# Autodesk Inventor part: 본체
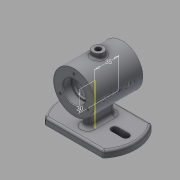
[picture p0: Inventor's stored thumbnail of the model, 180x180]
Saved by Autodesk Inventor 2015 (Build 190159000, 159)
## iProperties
Created: 2017-12
Part Number: 본체
Material: 일반
Document SubType Name: Modeling
Designer: SCD-A03
Density: 1 g/cm^3
Appearance: 기본값
Author: SCD-A03
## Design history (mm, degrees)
sketch "스케치1"
  geometry: L1 (-55, 0)-(55, 0); L2 (-42.426, 35)-(42.426, 35); L3 (-42.426, -35)-(42.426, -35); A1 r 55 centre (0, 0) between (-42.426, 35) and (-42.426, -35); A2 r 55 centre (0, 0) between (42.426, -35) and (42.426, 35); 1 further point
  constraints: 6 end point, 6 point on circle, 2 centre point, 2 parallel, 1 coincident, 1 horizontal
  dimensions: "d1" = 35 distance between parallel lines of L3 L1; "d2" = 35 distance between parallel lines of L2 L1
extrude "돌출1" new body sketch "스케치1" distance "d3" = 10; taper "d4" = 0 deg
sketch "스케치2"
  geometry: L1 (0, -15)-(0, 15); L2 (5, -15)-(5, 15); L3 (-5, 15)-(-5, -15); A1 r 55 centre (0, 0) between (42.426, -35) and (42.426, 35) reference; A2 r 5 centre (0, -15) between (-5, -15) and (5, -15); A3 r 5 centre (0, 15) between (5, 15) and (-5, 15)
  constraints: 8 end point, 4 point on circle, 4 tangent, 2 centre point, 1 midpoint, 1 parallel, 1 vertical
  dimensions: "d5" = 5 radius of A3; "d6" = 30 distance of L1.start L1.end
sketch "스케치6"
  geometry: C1 r 30 at (0, 62); 1 further point
  constraints: 1 centre point, 1 vertical alignment
  dimensions: "d18" = 60 diameter of C1; "d19" = 62 distance of point (0, 0) C1.centre
extrude "돌출5" join sketch "스케치6" stored distance "d20" = 70; taper "d21" = 0 deg
extrude "돌출6" join sketch "스케치2" stored distance "d22" = 70; taper "d23" = 0 deg
sketch "스케치7"
  geometry: L1 (-40, 0)-(-24, 0); L2 (-40, 5)-(-24, 5); L3 (-24, -5)-(-40, -5); A1 r 55 centre (0, 0) between (-42.426, 35) and (-42.426, -35) reference; A2 r 5 centre (-40, 0) between (-40, 5) and (-40, -5); A3 r 5 centre (-24, 0) between (-24, -5) and (-24, 5); 1 further point
  constraints: 8 end point, 4 point on circle, 4 tangent, 2 centre point, 1 horizontal, 1 horizontal alignment, 1 midpoint, 1 parallel
  dimensions: "d24" = 5 radius of A2; "d26" = 16 distance of L1.end L1.start; "d27" = 24 distance of A1.centre L1.end
extrude "돌출7" cut sketch "스케치7" distance "d28" = 70; taper "d29" = 0 deg
sketch "스케치8"
  geometry: L1 (35, 10)-(35, 0) reference; L2 (35, 0)-(-35, 0) reference; L3 (-35, 0)-(-35, 10) reference; L4 (-35, 10)-(-20, 10) reference; L5 (-20, 10)-(-20, 32) reference; L6 (-20, 32)-(-35, 32) reference; L7 (-35, 32)-(-35, 92) reference; L8 (-35, 92)-(35, 92) reference; L9 (35, 92)-(35, 32) reference; L10 (35, 32)-(20, 32) reference; L11 (20, 32)-(20, 10) reference; L12 (20, 10)-(35, 10) reference; L13 (35, 62)-(-35, 62); L14 (-35, 62)-(-35, 78); L15 (-23, 77.7)-(-23, 76); L16 (-23, 76)-(-20, 76); L17 (-20, 76)-(-20, 84); L18 (-17, 87)-(17, 87); L19 (20, 84)-(20, 76); L20 (20, 76)-(23, 76); L21 (23, 76)-(23, 77.7); L22 (23.3, 78)-(35, 78); L23 (-23.3, 78)-(-35, 78); A1 r 3 centre (-17, 84) between (-17, 87) and (-20, 84); A2 r 3 centre (17, 84) between (20, 84) and (17, 87); A3 r 0.3 centre (-23.3, 77.7) between (-23, 77.7) and (-23.3, 78); A4 r 0.3 centre (23.3, 77.7) between (23.3, 78) and (23, 77.7); 5 further points
  constraints: 22 end point, 12 point on line, 8 point on circle, 8 tangent, 6 perpendicular, 4 centre point, 2 equal radius, 2 midpoint, 1 horizontal, 1 vertical
  dimensions: "d30" = 32 diameter of L23 L13; "d31" = 28 diameter of L16 L13; "d32" = 50 diameter of L18 L13; "d33" = 32 diameter of L22 L13; "d34" = 12 distance of point (-23, 78) L14.end; "d35" = 40 distance of point (-20, 87) point (20, 87); "d36" = 3 distance of L15.end L16.end; "d37" = 12 distance of point (23, 78) L22.end; "d38" = 70 distance of L14.end L22.end (derived); "d66" = 3 radius of A1; "d67" = 0.3 radius of A3
revolve "회전1" sketch "스케치8" stored, may be unused: angle "d39" = 90 deg
node "작업 평면1"
sketch "스케치9"
  geometry: L1 (-30, -35)-(30, -35) reference; C1 r 8 at (0, 0); 1 further point
  constraints: 1 centre point, 1 coincident
  dimensions: "d41" = 16 diameter of C1
extrude "돌출8" join sketch "스케치9" stored distance "d42" = 70; taper "d43" = 0 deg
sketch "스케치10"
  geometry: C1 r 8 at (0, 0) reference
hole "구멍1" sketch "스케치10" at (0, 0) diameter "d44" = 8; stored, may be unused: countersink angle "d48" = 90 deg, drill point angle "d50" = 118 deg; dims "d45" = 6, "d46" = 4, "d47" = 2, "d49" = 30
sketch "스케치11"
  geometry: C1 r 16 at (0, 0) reference; 2 further points
  constraints: 1 vertical alignment
  dimensions: "d51" = 23 distance of C1.centre point (0, 23)
hole "구멍2" sketch "스케치11" at (0, 23) diameter "d52" = 3.242; stored, may be unused: countersink angle "d56" = 90 deg, drill point angle "d58" = 118 deg; dims "d53" = 8, "d54" = 4, "d55" = 2, "d57" = 10
fillet "모깎기1" dims "d62" = 5
fillet "모깎기2" dims "d63" = 3
fillet "모깎기3" dims "d64" = 3
fillet "모깎기4" dims "d65" = 3
chamfer "모따기1" distance "d68" = 1; stored, may be unused: second distance "d69" = 2, angle "d70" = 45 deg
node "작업 평면2"
sketch "스케치12"
  geometry: L1 (-35, 92)-(-35, 32) reference; 2 further points
  constraints: 1 other
  dimensions: "d72" = 35 distance from line of point (0, 62) L1; "d73" = 30 vertical distance of L1.start point (0, 62)
node "솔리드1"
mirror "대칭1"
pattern_circular "원형 패턴1" dims angle "d60" = 360 deg
mirror "대칭2"
node "절단 모서리 투영1"
other parameters: "d40" = -99
